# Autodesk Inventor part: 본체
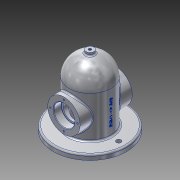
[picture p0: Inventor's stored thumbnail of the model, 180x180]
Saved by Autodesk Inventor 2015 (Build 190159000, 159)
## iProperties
Created: 2019-11
Part Number: 본체
Material: 알루미늄 6061
Document SubType Name: Modeling
Designer: now
Density: 2.7 g/cm^3
Appearance: 알루미늄 - 평지
Mass: 1106.12 g
Surface Area: 883.263 cm^2
Volume: 409.676 cm^3
Author: now
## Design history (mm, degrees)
sketch "스케치1"
  geometry: C1 r 70 at (0, 0); 1 further point
  constraints: 1 centre point, 1 coincident
  dimensions: "d0" = 140 diameter of C1
extrude "돌출1" new body sketch "스케치1" distance "d1" = 10; taper "d2" = 0 deg
sketch "스케치2"
  geometry: C1 r 70 at (0, 0) reference; C2 r 40 at (0, 0)
  constraints: 1 centre point, 1 coincident
  dimensions: "d3" = 80 diameter of C2
extrude "돌출2" join sketch "스케치2" distance "d4" = 120; taper "d5" = 0 deg
fillet "모깎기1" dims "d6" = 40
feature "쉘1" dims "d7" = 10
node "작업 평면1"
sketch "스케치4"
  geometry: L1 (-70, 0)-(70, 0) reference; C1 r 31 at (0, 50); 1 further point
  constraints: 1 centre point, 1 vertical alignment
  dimensions: "d9" = 62 diameter of C1; "d10" = 50 distance from line of L1 C1.centre
extrude "돌출3" join sketch "스케치4" stored distance "d11" = 120; taper "d12" = 0 deg
sketch "스케치5"
  geometry: C1 r 31 at (0, 0) reference; 1 further point
hole "구멍1" sketch "스케치5" at (0, 0) diameter "d13" = 40; stored, may be unused: countersink angle "d17" = 90 deg, drill point angle "d19" = 0 deg; dims "d14" = 6, "d15" = 4, "d16" = 2, "d18" = 15
sketch "스케치6"
  geometry: C1 r 20 at (0, 0) reference; 1 further point
hole "구멍2" sketch "스케치6" at (0, 0) diameter "d20" = 33; stored, may be unused: countersink angle "d24" = 90 deg, drill point angle "d26" = 0 deg; dims "d21" = 6, "d22" = 4, "d23" = 2, "d25" = 35
node "작업 평면2"
sketch "스케치7"
  geometry: C1 r 7.5 at (0, 0); 1 further point
  constraints: 1 centre point, 1 coincident
  dimensions: "d28" = 15 diameter of C1
extrude "돌출4" join sketch "스케치7" stored distance "d29" = 120; taper "d30" = 0 deg
sketch "스케치8"
  geometry: C1 r 7.5 at (0, 0) reference
hole "구멍3" sketch "스케치8" at (0, 0) diameter "d31" = 5.188; stored, may be unused: countersink angle "d35" = 90 deg, drill point angle "d37" = 0 deg; dims "d32" = 12, "d33" = 4, "d34" = 2, "d36" = 40
sketch "스케치9"
  geometry: C1 r 20 at (0, 0) reference; 2 further points
  constraints: 1 vertical alignment
  dimensions: "d38" = 26 distance of C1.centre point (0, 26)
hole "구멍4" sketch "스케치9" at (0, 26) diameter "d39" = 3.242; stored, may be unused: countersink angle "d43" = 90 deg, drill point angle "d45" = 118 deg; dims "d40" = 8, "d41" = 4, "d42" = 2, "d44" = 10
fillet "모깎기2" dims "d49" = 0.3
sketch "스케치10"
  geometry: C1 r 40 at (0, 0) reference; 2 further points
  constraints: 2 horizontal alignment
  dimensions: "d50" = 55 distance of C1.centre point (-55, 0); "d51" = 55 distance of C1.centre point (55, 0)
hole "구멍5" sketch "스케치10" at (-55, 0), (55, 0) diameter "d52" = 9; stored, may be unused: countersink angle "d56" = 90 deg, drill point angle "d58" = 118 deg; dims "d53" = 8, "d54" = 4, "d55" = 2, "d57" = 10
fillet "모깎기3" dims "d59" = 3
chamfer "모따기1" distance "d60" = 1; stored, may be unused: second distance "d61" = 2, angle "d62" = 45 deg
node "작업 평면4"
sketch "스케치12"
  geometry: L1 (-70, 0)-(70, 0) reference; 2 further points
  constraints: 1 vertical alignment, 1 other
  dimensions: "d66" = 50 distance from line of L1 point (0, 50)
feature "엠보싱1" sketch "스케치12" dims "d67" = 0.5, "d68" = 0
fillet "모깎기4" dims "d69" = 3
node "솔리드1"
mirror "대칭1"
mirror "대칭2"
pattern_circular "원형 패턴1" dims angle "d47" = 360 deg
mirror "대칭3"
other parameters: "d27" = 135, "d65" = 40.5
